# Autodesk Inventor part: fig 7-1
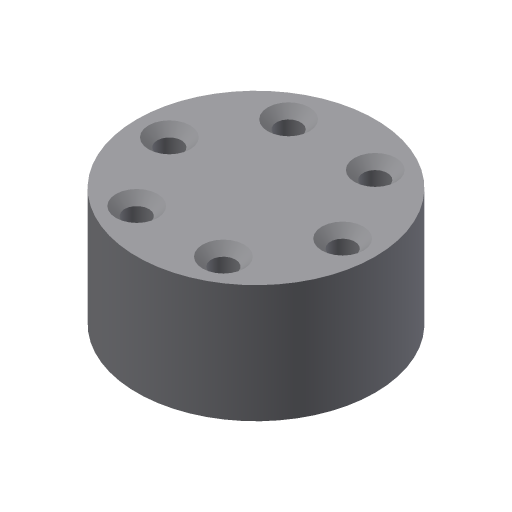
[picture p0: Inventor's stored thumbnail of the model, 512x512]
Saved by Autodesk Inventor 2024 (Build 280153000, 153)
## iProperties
Created: 2004-05
Part Number: fig 7-1
Document SubType Name: Modeling
Designer: CADCIM Technologies
Manufacturer: Standard
Standards Organization: Custom
Density: 1 g/cm^3
Material: Generic
Appearance: Default
Author: CADCIM Technologies
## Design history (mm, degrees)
sketch "Sketch1"
  geometry: C1 r 17.175 at (0, 0)
  constraints: 1 centre point
extrude "Extrusion1" new body sketch "Sketch1" distance "d0" = 17; taper "d1" = 0 deg
sketch "Sketch2"
  geometry: 1 further point
hole "Hole1" sketch "Sketch2" at (12.571, -0.074) diameter "d2" = 3.5; stored, may be unused: countersink angle "d6" = 90 deg, drill point angle "d8" = 118 deg; dims "d3" = 6, "d4" = 6, "d5" = 2, "d7" = 8
pattern_circular "Circular Pattern1" dims angle "d11" = 360 deg
body "Solid1"
